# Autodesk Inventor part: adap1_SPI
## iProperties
Created: 2006-11
Part Number: adap1_SPI
Material: Steel
Document SubType Name: Sheet Metal
Designer: WINDGES
Author: WINDGES
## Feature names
1. Abgeleiteter Körper1 [Tagging]
